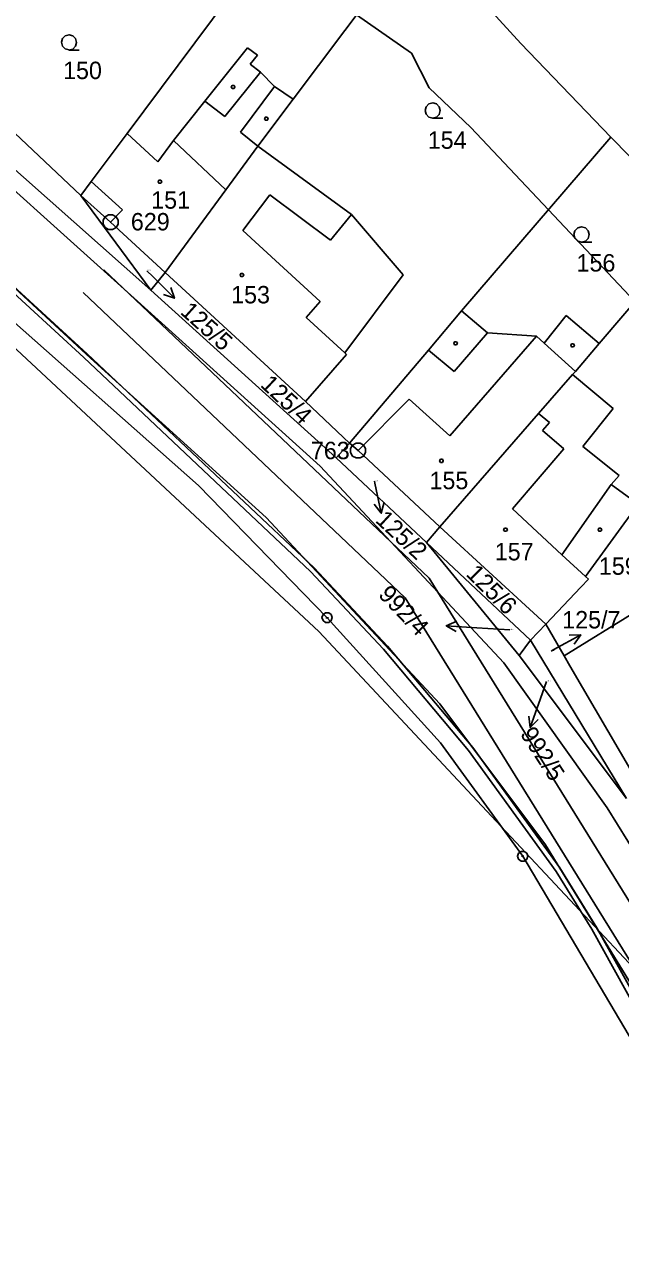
# Model space of a CAD drawing. Extents: x -755359 to -754474, y -1162585 to -1161655.
# Drawn here: x -754872 to -754813.8, y -1161904.8 to -1161783.9 of the extents above; entities that cross this region are included whole.
import ezdxf

# ---------------------------------------------------------------- set-up
doc = ezdxf.new("R2010")
doc.units = 0
for name, color, linetype in [('Vrstva 1', 7, 'Continuous'), ('Vrstva 11', 7, 'Continuous'), ('Vrstva 12', 7, 'Continuous'), ('Vrstva 13', 7, 'Continuous'), ('Vrstva 2', 7, 'Continuous'), ('Vrstva 3', 7, 'Continuous'), ('Vrstva 4', 7, 'Continuous'), ('Vrstva 5', 7, 'Continuous'), ('Vrstva 7', 7, 'Continuous'), ('Vrstva 8', 7, 'Continuous')]:
    doc.layers.add(name, color=color, linetype=linetype)

msp = doc.modelspace()

# ---------------------------------------------------------------- linework, layer by layer
at = {"layer": 'Vrstva 1'}
for p, q in [((-754953.69, -1161741.58), (-754855.01, -1161828.87)), ((-754861.99, -1161794.51), (-754846.5, -1161773.77)), ((-754833.48, -1161774.78), (-754845.76, -1161791.14)), ((-754833.48, -1161774.78), (-754823.5, -1161785.69)), ((-754882.65, -1161785.33), (-754866.5, -1161800.56)), ((-754850.23, -1161786.13), (-754854.38, -1161791.33)), ((-754849.24, -1161786.86), (-754850.23, -1161786.13)), ((-754849.95, -1161787.73), (-754849.24, -1161786.86)), ((-754823.5, -1161785.69), (-754814.71, -1161794.87)), ((-754848.96, -1161788.52), (-754849.95, -1161787.73)), ((-754859.67, -1161809.81), (-754883.24, -1161788.9)), ((-754847.59, -1161789.9), (-754848.96, -1161788.52)), ((-754845.76, -1161791.14), (-754847.59, -1161789.9)), ((-754854.38, -1161791.33), (-754857.45, -1161795.19)), ((-754849.21, -1161795.73), (-754845.76, -1161791.14)), ((-754865.48, -1161799.19), (-754861.99, -1161794.51)), ((-754858.98, -1161797.27), (-754861.99, -1161794.51)), ((-754857.45, -1161795.19), (-754858.98, -1161797.27)), ((-754814.71, -1161794.87), (-754829.3, -1161811.83)), ((-754806.13, -1161803.63), (-754814.71, -1161794.87)), ((-754852.33, -1161799.99), (-754849.21, -1161795.73)), ((-754849.21, -1161795.73), (-754840.05, -1161802.42)), ((-754866.5, -1161800.56), (-754865.48, -1161799.19)), ((-754858.25, -1161808.07), (-754852.33, -1161799.99)), ((-754866.5, -1161800.56), (-754863.59, -1161803.15)), ((-754866.5, -1161800.56), (-754859.67, -1161809.81)), ((-754840.05, -1161802.42), (-754835.01, -1161808.29)), ((-754863.59, -1161803.15), (-754858.25, -1161808.07)), ((-754815.87, -1161815.02), (-754806.13, -1161803.63)), ((-754858.25, -1161808.07), (-754859.67, -1161809.81)), ((-754844.55, -1161820.66), (-754858.25, -1161808.07)), ((-754835.01, -1161808.29), (-754840.72, -1161815.93)), ((-754841.94, -1161825.83), (-754859.67, -1161809.81)), ((-754829.3, -1161811.83), (-754832.54, -1161815.66)), ((-754826.77, -1161813.97), (-754829.3, -1161811.83)), ((-754819.08, -1161812.27), (-754821.23, -1161814.97)), ((-754815.87, -1161815.02), (-754819.08, -1161812.27)), ((-754821.97, -1161814.3), (-754826.77, -1161813.97)), ((-754821.23, -1161814.97), (-754821.97, -1161814.3)), ((-754832.54, -1161815.66), (-754840.24, -1161824.73)), ((-754818.18, -1161817.73), (-754815.87, -1161815.02)), ((-754840.54, -1161816.09), (-754844.55, -1161820.66)), ((-754840.72, -1161815.93), (-754840.54, -1161816.09)), ((-754821.79, -1161821.86), (-754818.47, -1161818.05)), ((-754818.47, -1161818.05), (-754818.18, -1161817.73)), ((-754814.49, -1161821.36), (-754818.47, -1161818.05)), ((-754840.24, -1161824.73), (-754844.55, -1161820.66)), ((-754831.41, -1161832.91), (-754821.79, -1161821.86)), ((-754817.47, -1161825.06), (-754814.49, -1161821.36)), ((-754840.24, -1161824.73), (-754841.56, -1161826.18)), ((-754840.24, -1161824.73), (-754839.41, -1161825.46)), ((-754839.41, -1161825.46), (-754831.41, -1161832.91)), ((-754813.89, -1161827.91), (-754817.47, -1161825.06)), ((-754841.56, -1161826.18), (-754841.94, -1161825.83)), ((-754832.73, -1161834.46), (-754841.56, -1161826.18)), ((-754814.68, -1161828.79), (-754813.89, -1161827.91)), ((-754855.01, -1161828.87), (-754842.43, -1161841.79)), ((-754812.05, -1161830.7), (-754814.68, -1161828.79)), ((-754817.18, -1161837.76), (-754812.05, -1161830.7)), ((-754831.41, -1161832.91), (-754832.73, -1161834.46)), ((-754831.41, -1161832.91), (-754821.08, -1161842.44)), ((-754832.73, -1161834.46), (-754823.68, -1161845.48)), ((-754822.56, -1161844), (-754832.73, -1161834.46)), ((-754821.08, -1161842.44), (-754817.66, -1161838.81)), ((-754817.66, -1161838.81), (-754816.89, -1161838.03)), ((-754816.89, -1161838.03), (-754817.18, -1161837.76)), ((-754819.29, -1161845.52), (-754812.21, -1161841.14)), ((-754842.43, -1161841.79), (-754831.37, -1161854.01)), ((-754821.08, -1161842.44), (-754822.56, -1161844)), ((-754821.08, -1161842.44), (-754819.29, -1161845.52)), ((-754823.68, -1161845.48), (-754822.56, -1161844)), ((-754813.2, -1161859.46), (-754822.56, -1161844)), ((-754823.68, -1161845.48), (-754813.2, -1161859.46)), ((-754819.29, -1161845.52), (-754818.72, -1161846.5)), ((-754812.54, -1161857.08), (-754818.72, -1161846.5)), ((-754831.37, -1161854.01), (-754823.33, -1161865.1)), ((-754823.33, -1161865.1), (-754790.69, -1161920.17))]:
    msp.add_line(p, q, dxfattribs=at)
at = {"layer": 'Vrstva 11'}
for p, q in [((-754839.58, -1161782.9), (-754834.21, -1161786.66)), ((-754905.2, -1161785.42), (-754843.26, -1161843.14)), ((-754834.21, -1161786.66), (-754832.47, -1161790.02)), ((-754832.47, -1161790.02), (-754828.39, -1161793.91)), ((-754828.39, -1161793.91), (-754820.81, -1161801.96)), ((-754820.81, -1161801.96), (-754812.37, -1161810.92)), ((-754843.26, -1161843.14), (-754825.44, -1161862.19)), ((-754825.44, -1161862.19), (-754802.43, -1161886.78))]:
    msp.add_line(p, q, dxfattribs=at)
at = {"layer": 'Vrstva 12'}
for p, q in [((-754865.48, -1161799.19), (-754861.99, -1161794.51)), ((-754858.98, -1161797.27), (-754861.99, -1161794.51)), ((-754857.45, -1161795.19), (-754858.98, -1161797.27)), ((-754857.45, -1161795.19), (-754852.33, -1161799.99)), ((-754852.33, -1161799.99), (-754849.21, -1161795.73)), ((-754849.21, -1161795.73), (-754840.05, -1161802.42)), ((-754865.48, -1161799.19), (-754862.43, -1161801.96)), ((-754858.25, -1161808.07), (-754852.33, -1161799.99)), ((-754858.25, -1161808.07), (-754852.33, -1161799.99)), ((-754850.66, -1161803.98), (-754848.05, -1161800.48)), ((-754848.05, -1161800.48), (-754842.11, -1161804.93)), ((-754862.43, -1161801.96), (-754863.59, -1161803.15)), ((-754842.11, -1161804.93), (-754840.05, -1161802.42)), ((-754863.59, -1161803.15), (-754858.25, -1161808.07)), ((-754843.11, -1161810.92), (-754850.66, -1161803.98)), ((-754844.55, -1161820.66), (-754858.25, -1161808.07)), ((-754844.49, -1161812.46), (-754843.11, -1161810.92)), ((-754840.72, -1161815.93), (-754844.49, -1161812.46)), ((-754821.97, -1161814.3), (-754830.44, -1161824.03)), ((-754821.23, -1161814.97), (-754821.97, -1161814.3)), ((-754821.23, -1161814.97), (-754818.18, -1161817.73)), ((-754840.54, -1161816.09), (-754844.55, -1161820.66)), ((-754840.72, -1161815.93), (-754840.54, -1161816.09)), ((-754821.79, -1161821.86), (-754818.47, -1161818.05)), ((-754818.47, -1161818.05), (-754818.18, -1161817.73)), ((-754834.41, -1161820.45), (-754839.41, -1161825.46)), ((-754830.44, -1161824.03), (-754834.41, -1161820.45)), ((-754831.41, -1161832.91), (-754821.79, -1161821.86)), ((-754831.41, -1161832.91), (-754821.79, -1161821.86)), ((-754821.79, -1161821.86), (-754820.7, -1161822.71)), ((-754820.7, -1161822.71), (-754821.4, -1161823.5)), ((-754821.4, -1161823.5), (-754819.3, -1161825.31)), ((-754839.41, -1161825.46), (-754831.41, -1161832.91)), ((-754819.3, -1161825.31), (-754824.33, -1161831.17)), ((-754824.33, -1161831.17), (-754819.49, -1161835.64)), ((-754831.41, -1161832.91), (-754821.08, -1161842.44)), ((-754819.49, -1161835.64), (-754817.18, -1161837.76)), ((-754821.08, -1161842.44), (-754817.66, -1161838.81)), ((-754817.66, -1161838.81), (-754816.89, -1161838.03)), ((-754816.89, -1161838.03), (-754817.18, -1161837.76)), ((-754819.29, -1161845.52), (-754812.21, -1161841.14)), ((-754819.29, -1161845.52), (-754818.72, -1161846.5)), ((-754812.54, -1161857.08), (-754818.72, -1161846.5))]:
    msp.add_line(p, q, dxfattribs=at)
at = {"layer": 'Vrstva 13'}
for p, q in [((-754885.85, -1161797.69), (-754865.87, -1161816.03)), ((-754866.21, -1161816.39), (-754886.19, -1161798.05)), ((-754864.27, -1161807.82), (-754864.27, -1161807.82)), ((-754864.27, -1161807.82), (-754832.48, -1161837.94)), ((-754866.29, -1161810.04), (-754866.29, -1161810.04)), ((-754834.82, -1161839.85), (-754866.29, -1161810.04)), ((-754844.05, -1161837.29), (-754866.21, -1161816.39)), ((-754865.87, -1161816.03), (-754843.7, -1161836.93)), ((-754836.94, -1161844.87), (-754844.05, -1161837.29)), ((-754843.7, -1161836.93), (-754836.54, -1161844.57)), ((-754832.48, -1161837.94), (-754785.36, -1161914.05)), ((-754788.28, -1161915.03), (-754834.82, -1161839.85)), ((-754828.63, -1161854.75), (-754836.94, -1161844.87)), ((-754836.54, -1161844.57), (-754828.21, -1161854.47)), ((-754828.21, -1161854.47), (-754819.71, -1161866.24)), ((-754820.07, -1161866.58), (-754828.63, -1161854.75)), ((-754816.58, -1161872.22), (-754820.07, -1161866.58)), ((-754819.71, -1161866.24), (-754816.08, -1161872.1)), ((-754809.61, -1161884.83), (-754816.58, -1161872.22)), ((-754816.08, -1161872.1), (-754809.17, -1161884.59))]:
    msp.add_line(p, q, dxfattribs=at)
at = {"layer": 'Vrstva 3'}
for points in [[(-754867.64, -1161786.33), (-754868.02, -1161786.23), (-754868.29, -1161785.96), (-754868.39, -1161785.59), (-754868.29, -1161785.22), (-754868.02, -1161784.95), (-754867.65, -1161784.85), (-754867.28, -1161784.95), (-754867.01, -1161785.22), (-754866.91, -1161785.6), (-754867.01, -1161785.98), (-754867.28, -1161786.25), (-754867.66, -1161786.35), (-754866.66, -1161786.35)], [(-754832.11, -1161792.99), (-754832.49, -1161792.89), (-754832.76, -1161792.62), (-754832.86, -1161792.25), (-754832.76, -1161791.88), (-754832.49, -1161791.61), (-754832.12, -1161791.51), (-754831.75, -1161791.61), (-754831.48, -1161791.88), (-754831.38, -1161792.26), (-754831.48, -1161792.64), (-754831.75, -1161792.91), (-754832.13, -1161793.01), (-754831.13, -1161793.01)], [(-754817.57, -1161805.1), (-754817.95, -1161805), (-754818.22, -1161804.73), (-754818.32, -1161804.36), (-754818.22, -1161803.99), (-754817.95, -1161803.72), (-754817.58, -1161803.62), (-754817.21, -1161803.72), (-754816.94, -1161803.99), (-754816.84, -1161804.37), (-754816.94, -1161804.75), (-754817.21, -1161805.02), (-754817.59, -1161805.12), (-754816.59, -1161805.12)]]:
    msp.add_lwpolyline(points, dxfattribs=at)
at = {"layer": 'Vrstva 4'}
for p, q in [((-754848.96, -1161788.52), (-754852.42, -1161792.85)), ((-754883.79, -1161790.36), (-754860.97, -1161810.87)), ((-754847.59, -1161789.9), (-754850.91, -1161794.38)), ((-754852.42, -1161792.85), (-754854.38, -1161791.33)), ((-754865.57, -1161816.45), (-754888.68, -1161795.04)), ((-754857.45, -1161795.19), (-754852.33, -1161799.99)), ((-754850.91, -1161794.38), (-754849.21, -1161795.73)), ((-754865.48, -1161799.19), (-754862.43, -1161801.96)), ((-754850.66, -1161803.98), (-754848.05, -1161800.48)), ((-754848.05, -1161800.48), (-754842.11, -1161804.93)), ((-754862.43, -1161801.96), (-754863.59, -1161803.15)), ((-754842.11, -1161804.93), (-754840.05, -1161802.42)), ((-754843.11, -1161810.92), (-754850.66, -1161803.98)), ((-754843.11, -1161827), (-754860.97, -1161810.87)), ((-754844.49, -1161812.46), (-754843.11, -1161810.92)), ((-754840.72, -1161815.93), (-754844.49, -1161812.46)), ((-754821.97, -1161814.3), (-754830.44, -1161824.03)), ((-754830.01, -1161817.74), (-754826.77, -1161813.97)), ((-754832.54, -1161815.66), (-754830.01, -1161817.74)), ((-754821.23, -1161814.97), (-754818.18, -1161817.73)), ((-754865.57, -1161816.45), (-754848.39, -1161832.02)), ((-754834.41, -1161820.45), (-754839.41, -1161825.46)), ((-754830.44, -1161824.03), (-754834.41, -1161820.45)), ((-754821.79, -1161821.86), (-754820.7, -1161822.71)), ((-754820.7, -1161822.71), (-754821.4, -1161823.5)), ((-754821.4, -1161823.5), (-754819.3, -1161825.31)), ((-754819.3, -1161825.31), (-754824.33, -1161831.17)), ((-754825.18, -1161846.21), (-754843.11, -1161827)), ((-754819.49, -1161835.64), (-754814.68, -1161828.79)), ((-754824.33, -1161831.17), (-754819.49, -1161835.64)), ((-754848.39, -1161832.02), (-754831.41, -1161850.21)), ((-754819.49, -1161835.64), (-754817.18, -1161837.76)), ((-754815.09, -1161860.38), (-754825.18, -1161846.21)), ((-754831.41, -1161850.21), (-754821.11, -1161863.98)), ((-754806, -1161875.03), (-754815.09, -1161860.38)), ((-754821.11, -1161863.98), (-754807.06, -1161886.86))]:
    msp.add_line(p, q, dxfattribs=at)
at = {"layer": 'Vrstva 5'}
for points in [[(-754851.53, -1161789.8), (-754851.44, -1161789.95), (-754851.53, -1161790.1), (-754851.71, -1161790.1), (-754851.8, -1161789.95), (-754851.71, -1161789.8)], [(-754848.28, -1161792.9), (-754848.19, -1161793.05), (-754848.28, -1161793.2), (-754848.46, -1161793.2), (-754848.55, -1161793.05), (-754848.46, -1161792.9)], [(-754858.69, -1161799.06), (-754858.6, -1161799.21), (-754858.69, -1161799.36), (-754858.87, -1161799.36), (-754858.96, -1161799.21), (-754858.87, -1161799.06)], [(-754850.68, -1161808.17), (-754850.59, -1161808.32), (-754850.68, -1161808.47), (-754850.86, -1161808.47), (-754850.95, -1161808.32), (-754850.86, -1161808.17)], [(-754829.8, -1161814.83), (-754829.71, -1161814.98), (-754829.8, -1161815.13), (-754829.98, -1161815.13), (-754830.07, -1161814.98), (-754829.98, -1161814.83)], [(-754818.37, -1161815.05), (-754818.28, -1161815.2), (-754818.37, -1161815.35), (-754818.55, -1161815.35), (-754818.64, -1161815.2), (-754818.55, -1161815.05)], [(-754831.18, -1161826.32), (-754831.09, -1161826.47), (-754831.18, -1161826.62), (-754831.36, -1161826.62), (-754831.45, -1161826.47), (-754831.36, -1161826.32)], [(-754824.92, -1161833.05), (-754824.83, -1161833.2), (-754824.92, -1161833.35), (-754825.1, -1161833.35), (-754825.19, -1161833.2), (-754825.1, -1161833.05)], [(-754815.7, -1161833.05), (-754815.61, -1161833.2), (-754815.7, -1161833.35), (-754815.88, -1161833.35), (-754815.97, -1161833.2), (-754815.88, -1161833.05)]]:
    msp.add_lwpolyline(points, close=True, dxfattribs=at)
at = {"layer": 'Vrstva 7'}
for p, q in [((-754860.04, -1161807.9), (-754859.48, -1161808.47)), ((-754857.359, -1161810.591), (-754859.48, -1161808.47)), ((-754837.82, -1161828.47), (-754837.78, -1161828.65)), ((-754837.156, -1161831.584), (-754837.78, -1161828.65)), ((-754830.793, -1161842.571), (-754827.8, -1161842.78)), ((-754824.58, -1161842.98), (-754827.8, -1161842.78)), ((-754817.657, -1161843.454), (-754820.28, -1161844.91)), ((-754820.56, -1161845.06), (-754820.28, -1161844.91)), ((-754820.99, -1161848.01), (-754821.59, -1161849.69)), ((-754822.615, -1161852.51), (-754821.59, -1161849.69))]:
    msp.add_line(p, q, dxfattribs=at)
for points in [[(-754857.712, -1161809.531), (-754857.359, -1161810.591), (-754858.419, -1161810.238)], [(-754836.875, -1161830.502), (-754837.156, -1161831.584), (-754837.853, -1161830.71)], [(-754829.83, -1161843.139), (-754830.793, -1161842.571), (-754829.76, -1161842.142)], [(-754818.774, -1161843.502), (-754817.657, -1161843.454), (-754818.289, -1161844.377)], [(-754821.803, -1161851.74), (-754822.615, -1161852.51), (-754822.743, -1161851.399)]]:
    msp.add_lwpolyline(points, dxfattribs=at)
at = {"layer": 'Vrstva 8'}
for p, q in [((-754863.64, -1161803.15), (-754863.54, -1161803.15)), ((-754839.46, -1161825.46), (-754839.36, -1161825.46)), ((-754842.55, -1161841.79), (-754842.31, -1161841.79)), ((-754823.45, -1161865.1), (-754823.21, -1161865.1))]:
    msp.add_line(p, q, dxfattribs=at)
for points in [[(-754863.4, -1161802.43), (-754863.06, -1161802.62), (-754862.87, -1161802.96), (-754862.87, -1161803.35), (-754863.06, -1161803.69), (-754863.4, -1161803.88), (-754863.79, -1161803.88), (-754864.13, -1161803.69), (-754864.32, -1161803.35), (-754864.32, -1161802.96), (-754864.13, -1161802.62), (-754863.79, -1161802.43)], [(-754839.22, -1161824.74), (-754838.88, -1161824.93), (-754838.69, -1161825.27), (-754838.69, -1161825.66), (-754838.88, -1161826), (-754839.22, -1161826.19), (-754839.61, -1161826.19), (-754839.95, -1161826), (-754840.14, -1161825.66), (-754840.14, -1161825.27), (-754839.95, -1161824.93), (-754839.61, -1161824.74)], [(-754842.28, -1161841.31), (-754842.03, -1161841.49), (-754841.93, -1161841.78), (-754842.03, -1161842.07), (-754842.28, -1161842.25), (-754842.59, -1161842.25), (-754842.84, -1161842.07), (-754842.94, -1161841.78), (-754842.84, -1161841.49), (-754842.59, -1161841.31)], [(-754823.18, -1161864.62), (-754822.93, -1161864.8), (-754822.83, -1161865.09), (-754822.93, -1161865.38), (-754823.18, -1161865.56), (-754823.49, -1161865.56), (-754823.74, -1161865.38), (-754823.84, -1161865.09), (-754823.74, -1161864.8), (-754823.49, -1161864.62)]]:
    msp.add_lwpolyline(points, close=True, dxfattribs=at)

# ---------------------------------------------------------------- texts
at = {"layer": 'Vrstva 2'}
for s, height, p in [('150', 1.7, (-754868.237, -1161789.18)), ('154', 1.7, (-754832.607, -1161795.99)), ('151', 1.7, (-754859.627, -1161801.84)), ('156', 1.7, (-754818.067, -1161807.98)), ('125/5', 0.1, (-754860.017, -1161807.9)), ('153', 1.7, (-754851.817, -1161811.09)), ('155', 1.7, (-754832.437, -1161829.24)), ('125/2', 0.1, (-754837.797, -1161828.47)), ('157', 1.7, (-754826.057, -1161836.19)), ('159/2', 1.7, (-754815.886, -1161837.6)), ('992/4', 0.1, (-754824.566, -1161842.98)), ('125/7', 0.1, (-754820.537, -1161845.06)), ('992/5', 0.1, (-754820.976, -1161848.01))]:
    msp.add_text(s, height=height, dxfattribs=at).set_placement(p)
for s, rotation, p in [('125/4', 316.78836, (-754849.054, -1161819.139)), ('125/6', 315.01219, (-754828.952, -1161837.608))]:
    msp.add_text(s, height=1.7, rotation=rotation, dxfattribs=at).set_placement(p)
at = {"layer": 'Vrstva 7'}
for s, rotation, p in [('125/5', 317.99158, (-754856.876, -1161812.036)), ('125/2', 317.01755, (-754837.811, -1161832.38)), ('992/4', 313.98087, (-754837.526, -1161839.622)), ('992/5', 302.98008, (-754823.634, -1161853.144))]:
    msp.add_text(s, height=1.7, rotation=rotation, dxfattribs=at).set_placement(p)
msp.add_text('125/7', height=1.7, dxfattribs=at).set_placement((-754819.467, -1161842.84))
at = {"layer": 'Vrstva 8'}
for s, p in [('629', (-754861.613, -1161803.96)), ('763', (-754844.024, -1161826.31))]:
    msp.add_text(s, height=1.7, dxfattribs=at).set_placement(p)

doc.saveas('drawing.dxf')
